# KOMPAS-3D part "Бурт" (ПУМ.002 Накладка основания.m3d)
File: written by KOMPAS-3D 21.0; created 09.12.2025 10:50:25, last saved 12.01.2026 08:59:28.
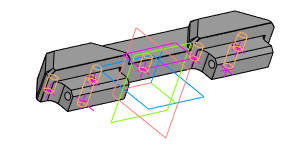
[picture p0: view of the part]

Document properties: Автор: User; Полное имя файла: C:\Users\User\Desktop\ПУ\ПУМ\ПУМ.002 Накладка основания.m3d

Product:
- Part/product: Бурт
    Материал: АМг6  ГОСТ 4784-2019 (density 2650 kg/m3)
    Масса: 0.258544

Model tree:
1. Эскиз:1
2. Элемент выдавливания:1
     Расстояние 1 = 27
3. Эскиз:2  (with: Элемент выдавливания:1)
4. Элемент выдавливания:2
     Расстояние 1 = 19
5. Эскиз:3  (with: Элемент выдавливания:1)
6. Элемент выдавливания:3
     Расстояние 1 = 14
7. Эскиз:5  (with: Элемент выдавливания:3, Элемент выдавливания:1)
8. Элемент выдавливания:4
     Расстояние 1 = 100; Расстояние 2 = 100
9. Эскиз:6  (with: Элемент выдавливания:3, Элемент выдавливания:1)
10. Отверстие:1  (with: Элемент выдавливания:3)  (labels: M6)
     Глубина выреза = 18; Диаметр отверстия = 4.91747; Угол конуса дна = 118; Расстояние 1 = 3.5; Расстояние 2 = 25
11. M6  (with: Элемент выдавливания:3)  (labels: M6; cil0_24705-2004 coarse)
     Длина резьбы = 20; Шаг резьбы = 1; Номинальный диаметр резьбы = 6
12. Отверстие:2  (with: Элемент выдавливания:3, M6)  (labels: M6; cil0_24705-2004 coarse)
     Глубина выреза = 17; Диаметр отверстия = 4.91747; Угол конуса дна = 118; Расстояние 1 = 3.5; Расстояние 2 = 25; Длина резьбы = 15; Шаг резьбы = 1; Номинальный диаметр резьбы = 6
13. Эскиз:7  (with: Элемент выдавливания:1)
14. Элемент выдавливания:5  (with: Элемент выдавливания:3)
15. Скругление:2  (with: Элемент выдавливания:1)
     Радиус = 2
16. Фаска:2  (with: Элемент выдавливания:1)
     Угол = 45; Длина 1 = 4; Длина 2 = 4
17. Фаска:3  (with: Элемент выдавливания:5)
     Угол = 45; Длина 1 = 2.5; Длина 2 = 2.5
18. Эскиз:8  (with: Элемент выдавливания:2)
19. Фаска:4  (with: Элемент выдавливания:3)
     Угол = 45; Длина 1 = 3; Длина 2 = 3
20. Скругление:3  (with: Элемент выдавливания:3)
     Радиус = 5
21. Фаска:5  (with: Элемент выдавливания:5, Скругление:2, Скругление:3, Элемент выдавливания:3, Элемент выдавливания:1, Фаска:2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)
     Угол = 45; Длина 1 = 0.2; Длина 2 = 0.2
22. Фаска:6  (with: Элемент выдавливания:1)
     Угол = 45; Длина 1 = 0.5; Длина 2 = 0.5
23. Эскиз:9  (with: Элемент выдавливания:3, Фаска:5)
24. Отверстие:3  (with: Элемент выдавливания:3, Фаска:5, M6)  (labels: M6; cil0_24705-2004 coarse)
     Глубина выреза = 12; Диаметр отверстия = 4.91747; Угол конуса дна = 118; Расстояние 1 = -183.8; Расстояние 2 = -8.8; Длина резьбы = 10; Шаг резьбы = 1; Номинальный диаметр резьбы = 6
25. Фаска:7  (with: Отверстие:2, Отверстие:1, Отверстие:3)
     Угол = 45; Длина 1 = 1; Длина 2 = 1
26. Массив по точкам:1
27. Экземпляр ( 4 )  (with: Отверстие:3, Эскиз:9)  (labels: 0x0,5)
28. Фаска:7
29. Экземпляр ( 1 )  (with: Отверстие:3, Эскиз:9)  (labels: 0x0,5)
30. Фаска:7
31. Экземпляр ( 2 )  (with: Отверстие:3, Эскиз:9)  (labels: 0x0,5)
32. Фаска:7
33. Экземпляр ( 3 )  (with: Отверстие:3, Эскиз:9)  (labels: 0x0,5)
34. Фаска:7  (labels: АМг6  ГОСТ 4784-2019)

Expressions: v799/2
